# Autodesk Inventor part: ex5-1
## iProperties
Shininess: 64.0
Length Units: 11272
Angle Units: 11279
Time Units: 11290
Mass Units: 11286
Length Display Precision: 3
Angle Display Precision: 2
Compacted: True
Part Number: ex5-1
Document SubType Name: Modeling
Created: 2002-09
Designer: Elise Moss
Density: 0.0
Volumn: 0.0
Area: 0.0
PropertySet Name: Model Information
Control State: 0
Master: False
Checked Out: False
Author: Elise Moss
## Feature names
1. Revolution1
